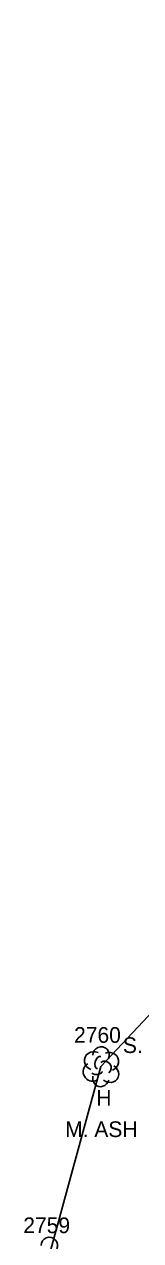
# Model space of a CAD drawing. Extents: x 1623612 to 1625808, y 621345 to 627748.
# Drawn here: x 1624741.5 to 1624756.3, y 626674 to 626828.8 of the extents above; entities that cross this region are included whole.
import ezdxf

# ---------------------------------------------------------------- set-up
doc = ezdxf.new("R2010")
doc.units = 0
for name, color, linetype in [('L_A', 7, 'Continuous'), ('L_C', 7, 'Continuous'), ('L_I', 7, 'Continuous'), ('LSOGP', 7, 'Continuous'), ('LTD', 7, 'Continuous')]:
    doc.layers.add(name, color=color, linetype=linetype)

msp = doc.modelspace()

# ---------------------------------------------------------------- linework, layer by layer
at = {"layer": 'LSOGP'}
msp.add_lwpolyline([(1624915.57, 627163.54), (1624896.56, 627076.5), (1624896.18, 627056.71), (1624892.58, 627023.76), (1624859.42, 627006.38), (1624857.36, 627007.43), (1624844.79, 627005.89), (1624844.65, 627005.84), (1624831.84, 626981.48), (1624823.33, 626945.82), (1624823.32, 626945.57), (1624824.67, 626942.88), (1624817.5, 626921.76), (1624817.2, 626921.82), (1624799.85, 626881.95), (1624797.4, 626842.57), (1624799.71, 626787.21), (1624789.17, 626757.26), (1624765.61, 626718.87), (1624765.58, 626718.79), (1624761.3, 626706.88), (1624751.21, 626696.18), (1624744.62, 626671.95)], dxfattribs=at)
at = {"layer": 'LTD'}
msp.add_line((1624751.21, 626696.18), (1624751.21, 626696.18), dxfattribs=at)
msp.add_line((1624751.21, 626696.18), (1624751.21, 626696.18), dxfattribs=at)
for centre in [(1624751.25, 626697.62), (1624744.67, 626673.38)]:
    msp.add_arc(centre, 1.05, 335.5272, 180.9563, dxfattribs=at)
for centre, major_axis, ratio, start_param, end_param in [((1624750.41, 626696.85), (1.21, -0.51), 0.895232, 1.570796, 4.712389), ((1624752.25, 626696.77), (-1.14, -0.48), 0.949671, 1.570796, 4.712389), ((1624750.12, 626695.47), (0.58, -1.04), 0.959034, 3.141593, 6.283185), ((1624751, 626696.64), (-0.208, -0.792), 0.645439, 3.141593, 6.283185), ((1624751.71, 626696.02), (-0.5, 0.667), 0.989748, 3.141593, 6.283185), ((1624752.21, 626695.35), (-1.09, 0.79), 0.841452, 1.570796, 4.712389), ((1624751.21, 626694.68), (0.26, 1.06), 0.942809, 1.570796, 4.712389), ((1624750.75, 626695.43), (-0.625, -0.083), 0.423636, 0, 3.141593)]:
    msp.add_ellipse(centre, major_axis=major_axis, ratio=ratio, start_param=start_param, end_param=end_param, dxfattribs=at)

# ---------------------------------------------------------------- texts
at = {"layer": 'L_A'}
msp.add_text('H', height=2, dxfattribs=at).set_placement((1624750.64, 626691.18))
at = {"layer": 'L_C'}
for s, p in [('S. SPRUCE', (1624754.02, 626697.88)), ('M. ASH', (1624746.67, 626687.18))]:
    msp.add_text(s, height=2, dxfattribs=at).set_placement(p)
at = {"layer": 'L_I'}
for s, p in [('2760', (1624747.81, 626699.18)), ('2759', (1624741.35, 626674.95))]:
    msp.add_text(s, height=2, dxfattribs=at).set_placement(p)

doc.saveas('drawing.dxf')
